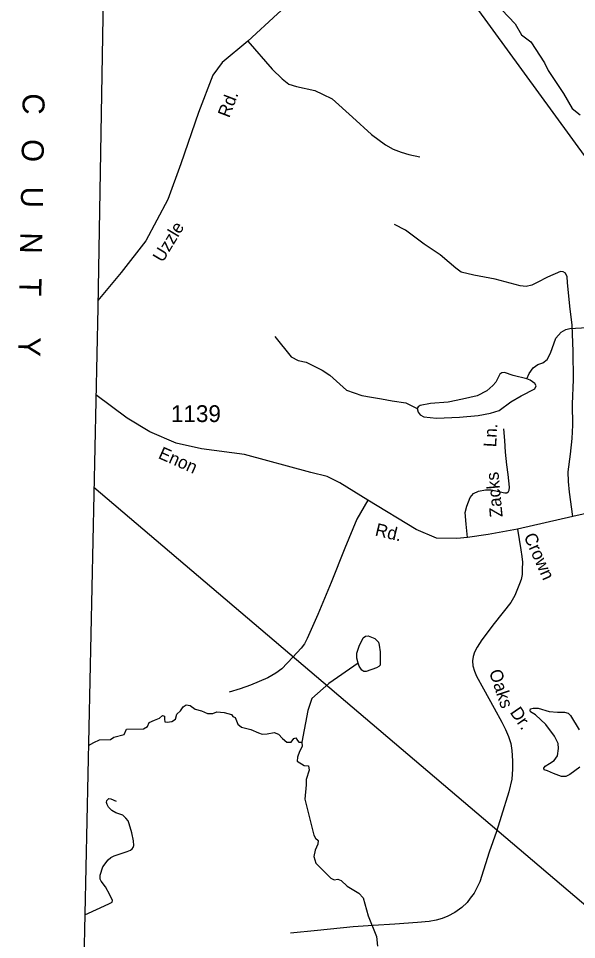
# Model space of a CAD drawing. Extents: x 2056842 to 2160602, y 826753 to 1016856.
# Drawn here: x 2057817 to 2061975, y 905308 to 912171 of the extents above; entities that cross this region are included whole.
import ezdxf

# ---------------------------------------------------------------- set-up
doc = ezdxf.new("R2010")
doc.units = 0
for name, color, linetype in [('Exist Boundary Political CountyLine', 7, 'Continuous'), ('Exist Boundary Political CountyLine Label', 7, 'Continuous'), ('Exist Hydrographic Creek Single Shore', 7, 'Continuous'), ('Exist Hydrographic Misc Water Feature', 7, 'Continuous'), ('Exist Road Non-System Type 51', 7, 'Continuous'), ('Exist Road Non-System Type 51 Label', 7, 'Continuous'), ('Exist Road Secondary Type 41 Attributed', 7, 'Continuous'), ('Exist Road Secondary Type 51 Attributed', 7, 'Continuous'), ('Exist Road Secondary Type 51 Label', 7, 'Continuous'), ('Exist Road Secondary Type 51 Number Label', 7, 'Continuous'), ('Exist Utilities Electrical Transmission Line', 7, 'Continuous')]:
    doc.layers.add(name, color=color, linetype=linetype)

msp = doc.modelspace()

# ---------------------------------------------------------------- linework, layer by layer
at = {"layer": 'Exist Boundary Political CountyLine'}
msp.add_lwpolyline([(2059856.6, 1016190.3), (2059992.1, 1014583.5), (2060287.9, 1010619.4), (2060242.2, 1008370.9), (2060207.5, 1006770.5), (2060178.3, 1005306.3), (2060151, 1003993.9), (2060126.7, 1003051.7), (2060085.9, 1001469.5), (2060082.6, 1001042.9), (2059970.1, 996247.2), (2059900.3, 992964.9), (2059780.5, 986400.7), (2059706.7, 983126.5), (2059583, 976558.1), (2059387.4, 966719.6), (2059309.7, 963431.4), (2059197.6, 956451.1), (2059161.2, 955539), (2058926.7, 940379.5), (2058724.8, 928102.2), (2058408.1, 910016.3), (2058297.2, 904795.7)], dxfattribs=at)
at = {"layer": 'Exist Hydrographic Creek Single Shore'}
for points in [[(2061417.5, 912235.2), (2061518, 912131.4), (2061566, 912047.5), (2061634.2, 911995.7), (2061736.2, 911839.9), (2061764.2, 911784.1), (2061878.9, 911612), (2061942.6, 911500.5), (2062003.1, 911452.4)], [(2058338.8, 906754.3), (2058378.3, 906776), (2058420.1, 906797.3), (2058502.9, 906799.7), (2058528.6, 906815.9), (2058604.5, 906836.7), (2058621.6, 906875.7), (2058749.4, 906877.4), (2058779.2, 906896.6), (2058790.6, 906924.1), (2058831.5, 906942.1), (2058867.5, 906957.3), (2058890.3, 906977.3), (2058905.5, 906973.5), (2058905.5, 906949.7), (2058907.4, 906929.8), (2058926.4, 906927.9), (2058959.9, 906933.3), (2058988.2, 906949.3), (2058997.6, 906987.7), (2059024.2, 907013.4), (2059044.1, 907041.8), (2059066, 907058), (2059097.3, 907051.3), (2059134.8, 907025.7), (2059180.4, 907011.5), (2059226, 906993.4), (2059265.8, 906992.5), (2059294.8, 907004.8), (2059348.9, 907001), (2059403.5, 906984.6), (2059415.6, 906970.6), (2059431.5, 906962.1), (2059450.5, 906911.8), (2059478.1, 906889.9), (2059547.4, 906873.8), (2059605.3, 906849.1), (2059632.4, 906839.6), (2059669.4, 906841.5), (2059721.6, 906851.9), (2059754.8, 906837.7), (2059785.2, 906806.4), (2059816.6, 906778.8), (2059847.9, 906778.8), (2059867.8, 906805.4), (2059884.9, 906812.1), (2059896.3, 906790.2), (2059906.3, 906778.8), (2059929.1, 906779.8)], [(2059929.1, 906779.8), (2059931.9, 906746.5), (2059911, 906709.5), (2059896.8, 906665.8), (2059893.9, 906636.4), (2059946.6, 906605.1), (2059978.9, 906602.2), (2059982.7, 906570.9), (2059960.9, 906499.7), (2059959.9, 906460.9), (2059952, 906353), (2060018.6, 906087), (2060030.7, 906063.1), (2060050.5, 906047.1), (2060046.8, 906019.2), (2060026.8, 905975), (2060018.9, 905927.2), (2060033, 905877.1), (2060145.1, 905765.3), (2060169.1, 905753.4), (2060197.2, 905757.5), (2060221.2, 905747.4), (2060265.3, 905705.4), (2060353.2, 905653.6), (2060385.4, 905619.8), (2060423.6, 905485.9), (2060484, 905331.9), (2060492.1, 905257.9)]]:
    msp.add_lwpolyline(points, dxfattribs=at)
at = {"layer": 'Exist Hydrographic Misc Water Feature'}
for points in [[(2061603.8, 909486), (2061622.1, 909524.5), (2061651.9, 909568.7), (2061687.8, 909592.5), (2061724.3, 909604.4), (2061755.8, 909628.8), (2061780, 909676.7), (2061821.7, 909788.8), (2061859.6, 909833), (2061895.5, 909852.7), (2061925.4, 909861.2), (2062053.6, 909867.3)], [(2059727.9, 909800.9), (2059848, 909649.2), (2059902.2, 909623.1), (2059959.8, 909609.5), (2060080.2, 909551.5), (2060138.2, 909511.8), (2060262.2, 909402.1), (2060376.7, 909362), (2060446.6, 909350.2), (2060521.5, 909336.1), (2060600.7, 909322.9), (2060704, 909305.7), (2060787.1, 909263.5)], [(2061603.8, 909486), (2061503.7, 909510.4), (2061437.7, 909532.8), (2061417.9, 909531.5), (2061404.7, 909521), (2061391.5, 909494.5), (2061373, 909460.2), (2061350.6, 909435.1), (2061307, 909395.5), (2061234.5, 909359.9), (2061126.3, 909333.5), (2061018, 909312.3), (2060886.1, 909303.1), (2060810.9, 909285.9), (2060795, 909278), (2060787.1, 909263.5)], [(2060787.1, 909263.5), (2060796.4, 909238.4), (2060809.6, 909218.6), (2060837.3, 909202.7), (2060931, 909193.5), (2061102.5, 909200.1), (2061242.4, 909212), (2061334.8, 909229.1), (2061398.1, 909250.3), (2061486.5, 909313.7), (2061563, 909358.5), (2061664.6, 909410), (2061673.9, 909432.5), (2061664.6, 909451), (2061630.3, 909476.1), (2061603.8, 909486)], [(2060347.7, 907368.1), (2060337.5, 907403.7), (2060337.5, 907442.2), (2060354.8, 907493.9), (2060384.2, 907556.9), (2060402.4, 907569), (2060421.7, 907570), (2060472.4, 907550.8), (2060498.7, 907523.4), (2060503.8, 907502.1), (2060510.9, 907451.3), (2060510.9, 907351.9), (2060501.8, 907341.8), (2060485.6, 907333.6), (2060407.5, 907306.3), (2060390.2, 907306.3), (2060376, 907315.4), (2060354.8, 907344.8), (2060347.7, 907368.1)], [(2060347.7, 907368.1), (2060130.5, 907215.2), (2060002.8, 907102.9), (2059972.9, 907014.9), (2059929.1, 906779.8)], [(2061999.2, 906593.7), (2061925.4, 906537.5), (2061894.4, 906524.2), (2061863.4, 906524.2), (2061804.4, 906544.9), (2061758.6, 906564.1), (2061735, 906571.5), (2061732, 906584.8), (2061742.4, 906601.1), (2061773.4, 906618.8), (2061807.3, 906642.4), (2061833.9, 906677.9), (2061841.3, 906731.1), (2061838.3, 906769.5), (2061811.7, 906824.1), (2061745.3, 906909.8), (2061668.5, 906982.2), (2061633.1, 907004.3), (2061628.7, 907014.7), (2061631.6, 907026.5), (2061650.8, 907032.4), (2061689.2, 907032.4), (2061771.9, 907007.3), (2061833.9, 907001.4), (2061885.6, 907002.9), (2061913.6, 906995.5), (2061931.3, 906977.7), (2061994.8, 906871.4)]]:
    msp.add_lwpolyline(points, dxfattribs=at)
at = {"layer": 'Exist Road Non-System Type 51'}
for points in [[(2059526.9, 912001.3), (2059706.6, 911793.9), (2059780.9, 911721.4), (2059832.7, 911681.6), (2059889.8, 911662.6), (2060024.5, 911633.3), (2060081.5, 911607.3), (2060154.1, 911571.1), (2060306.2, 911436.3), (2060447, 911306.7), (2060550.7, 911228.9), (2060607.7, 911197.8), (2060668.2, 911173.6), (2060725.2, 911158.1), (2060808.1, 911140.8)], [(2061947.2, 908460.4), (2061922.5, 908641.7), (2061914.5, 908721.5), (2061913.5, 908793.7), (2061930.1, 908925.6), (2061942, 909042.4), (2061947.7, 909141.2), (2061944.4, 909297.8), (2061951.5, 909481.1), (2061951, 909689), (2061942.5, 909886.5), (2061926.3, 910027.1), (2061907.3, 910203.7), (2061905.4, 910245.4), (2061892.2, 910272), (2061875.1, 910283.4), (2061856.1, 910285.3), (2061759.2, 910243.5), (2061681.4, 910203.7), (2061641.5, 910184.7), (2061599.7, 910173.3), (2061554.1, 910179), (2061368, 910228.3), (2061209.5, 910258.7), (2061116.4, 910279.6), (2061076.5, 910310), (2061025.3, 910351.8), (2060957.9, 910410.6), (2060840.1, 910488.5), (2060701.5, 910593), (2060619.8, 910634.7)], [(2061161.5, 908304.7), (2061152, 908403.4), (2061146.3, 908488.9), (2061158.2, 908538.2), (2061182.9, 908602.8), (2061207.6, 908630.3), (2061244.6, 908649.3), (2061295.9, 908658.8), (2061338.6, 908658.8), (2061441.6, 908636), (2061456.8, 908637), (2061468.2, 908645.5), (2061473, 908656.9), (2061476.8, 908679.7), (2061465.4, 908773.7), (2061455.4, 908844.9), (2061445.9, 908939.9), (2061441.6, 909025.3), (2061433.5, 909113.6)], [(2060419.1, 908581.8), (2060339.2, 908439.7), (2060247.6, 908223.1), (2060147.1, 907968.9), (2060048.8, 907729), (2059968.3, 907550.2), (2059947.2, 907510.3), (2059923.9, 907480.3), (2059862.3, 907411.4), (2059780.6, 907325.9), (2059734, 907293.7), (2059674, 907259.3), (2059545.8, 907202.7), (2059469.2, 907174.9), (2059387, 907150.5)], [(2061534.3, 908365.3), (2061559.5, 908212.6), (2061567.6, 908162.6), (2061571.5, 908119.3), (2061571.2, 908068.8), (2061569.5, 908028.8), (2061561.8, 907990.5), (2061550.1, 907958.3), (2061514.6, 907871.7), (2061484.6, 907818.9), (2061361.3, 907662.4), (2061269.7, 907540.2), (2061234.2, 907486.9), (2061214.2, 907448.1), (2061205.3, 907418.1), (2061200.9, 907385.9), (2061203.1, 907348.1), (2061214.2, 907307), (2061229.7, 907270.4), (2061282.5, 907177.1), (2061361.3, 907032.8), (2061418.5, 906928.4), (2061446.3, 906872.9), (2061468.5, 906820.7), (2061484.6, 906769.6), (2061492.4, 906716.3), (2061499, 906640.8), (2061499, 906576.4), (2061493.5, 906503.1), (2061470.2, 906409.8), (2061414.6, 906224.4), (2061379.7, 906112.2), (2061324.1, 905960.1), (2061254.7, 905738), (2061211.4, 905653.6), (2061182.6, 905615.9), (2061159.2, 905584.8), (2061121.5, 905548.1), (2061068.2, 905509.3), (2061017.1, 905482.6), (2060974.9, 905466), (2060930.5, 905452.6), (2060878.3, 905441.5), (2060789.5, 905436), (2060622.3, 905423.8), (2060460.8, 905412.7), (2060310.9, 905402.7), (2060044.4, 905376), (2059845, 905354.9)], [(2058312, 905493.2), (2058425.1, 905545.5), (2058495.8, 905576.4), (2058516.2, 905587.6), (2058517.5, 905598.1), (2058498.4, 905642.1), (2058464.6, 905702), (2058433.7, 905742.1), (2058426.1, 905759.2), (2058425.4, 905788.1), (2058446.8, 905849.3), (2058486.3, 905902.5), (2058506.6, 905919.6), (2058529.7, 905932.1), (2058583.6, 905949.9), (2058626, 905963), (2058652.9, 905974.8), (2058665.4, 905984), (2058672.7, 905993.9), (2058677.3, 906009.7), (2058674, 906044.5), (2058661.2, 906104.4), (2058642.4, 906170.8), (2058633.9, 906193.1), (2058618.1, 906212.2), (2058595.1, 906234.6), (2058542.2, 906252.3), (2058511.9, 906270.7), (2058488.2, 906295.7), (2058477.7, 906314.8), (2058473.8, 906330.5), (2058476.4, 906343.7), (2058490.9, 906358.2), (2058506.6, 906356.8), (2058544.1, 906339.8)]]:
    msp.add_lwpolyline(points, dxfattribs=at)
at = {"layer": 'Exist Road Secondary Type 41 Attributed'}
msp.add_lwpolyline([(2061270.4, 912701.4), (2060875.6, 912735.4), (2060723.1, 912741.8), (2060639.6, 912741.4), (2060592.8, 912738), (2060499.7, 912715.8), (2060282.4, 912631.4), (2060075.9, 912502), (2059746.4, 912204.6), (2059526.9, 912001.3), (2059336.1, 911842.5), (2059266.1, 911749.1), (2059158.3, 911468.8), (2059026.4, 911086.9), (2058929.4, 910822.8), (2058765.1, 910512.8), (2058581.9, 910277.5), (2058409, 910069)], dxfattribs=at)
at = {"layer": 'Exist Road Secondary Type 51 Attributed'}
msp.add_lwpolyline([(2063661.1, 908648.4), (2063408.8, 908696.4), (2063193.3, 908712.6), (2063058.5, 908709), (2062882.5, 908676.6), (2062292.4, 908537.3), (2061947.2, 908460.4), (2061534.3, 908365.3), (2061315.8, 908327), (2061161.5, 908304.7), (2061082.6, 908295.5), (2060931.7, 908299.1), (2060780.8, 908362), (2060419.1, 908581.8), (2060212.3, 908709.9), (2060117.1, 908758.4), (2059994.9, 908787.1), (2059500.1, 908921.1), (2059182.1, 908964.2), (2058991.7, 909005.5), (2058795.9, 909090), (2058626.1, 909191.6), (2058394.3, 909366.6)], dxfattribs=at)
at = {"layer": 'Exist Utilities Electrical Transmission Line'}
for points in [[(2070228.8, 900032.1), (2067062.6, 904400.1), (2063349.2, 909346.5), (2058512.6, 915983.7)], [(2070228.8, 900032.1), (2068476.6, 901324), (2068009.4, 901520.9), (2066435.5, 902603.7), (2065648.6, 902726.7), (2063521.4, 904301.7), (2058379.6, 908676.4)]]:
    msp.add_lwpolyline(points, dxfattribs=at)

# ---------------------------------------------------------------- texts
at = {"layer": 'Exist Boundary Political CountyLine Label'}
msp.add_text('C   O   U   N   T     Y', height=164.042, rotation=269.03226, dxfattribs=at).set_placement((2057849.1, 911613.8))
at = {"layer": 'Exist Road Non-System Type 51 Label'}
for s, rotation, p in [('Ln.', 86.90528, (2061376.1, 908974.9)), ('Zacks', 95.4509, (2061425.1, 908458)), ('Crown', 293.92961, (2061579.8, 908312.7)), ('Oaks', 288.54095, (2061321.7, 907303.6)), ('Dr.', 304.43948, (2061475.2, 907000.7))]:
    msp.add_text(s, height=95, rotation=rotation, dxfattribs=at).set_placement(p)
at = {"layer": 'Exist Road Secondary Type 51 Label'}
for s, rotation, p in [('Rd.', 69.05947, (2059387.3, 911425)), ('Uzzle', 59.03359, (2058892.4, 910347.5)), ('Enon', 336.06088, (2058852.2, 908896.8)), ('Rd.', 346.60659, (2060468.5, 908319.7))]:
    msp.add_text(s, height=95, rotation=rotation, dxfattribs=at).set_placement(p)
at = {"layer": 'Exist Road Secondary Type 51 Number Label'}
msp.add_text('1139', height=125, dxfattribs=at).set_placement((2058953.5, 909163.8))

doc.saveas('drawing.dxf')
